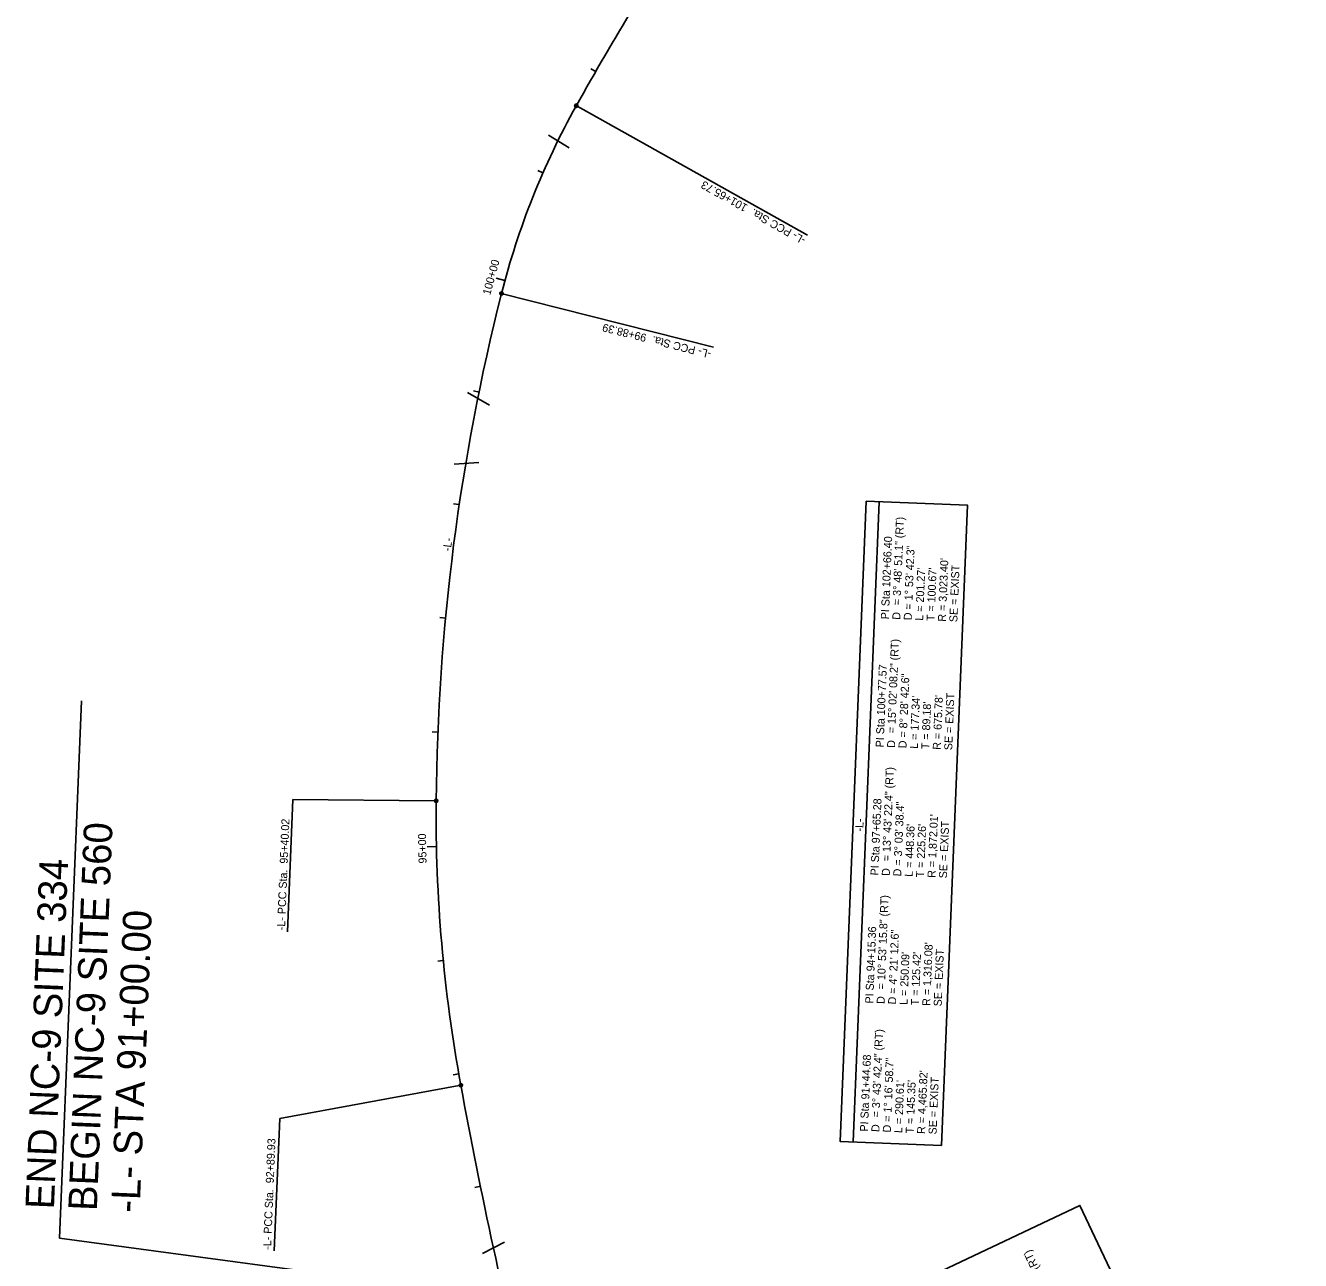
# Model space of a CAD drawing. Extents: x 1019959 to 1023888, y 635993 to 644996.
# Drawn here: x 1022230 to 1023345, y 641988 to 643068 of the extents above; entities that cross this region are included whole.
import ezdxf

# ---------------------------------------------------------------- set-up
doc = ezdxf.new("R2010")
doc.units = 0
for name, color, linetype in [('Cogo Default Point CELL', 7, 'Continuous'), ('COGO Default Point Elevation', 7, 'Continuous'), ('COGO Default Point Number', 7, 'Continuous'), ('Exist Other Culture Well CELL', 7, 'Continuous'), ('Exist Roads EOT', 7, 'Continuous'), ('Exist Structure Minor Pipes CMP 18 Inch Cogo Number', 7, 'Continuous'), ('Exist Structure Minor Pipes CMP 24 Inch Cogo Number', 7, 'Continuous'), ('Exist Utilities Power Pole CELL', 7, 'Continuous'), ('Exist Utilities Power Pole Cogo Elevation', 7, 'Continuous'), ('Exist Utilities Power Pole Cogo Number', 7, 'Continuous')]:
    doc.layers.add(name, color=color, linetype=linetype)

msp = doc.modelspace()

# ---------------------------------------------------------------- linework, layer by layer
at = {"layer": 'COGO Default Point Elevation'}
for p, q in [((1022728.6, 643027.5), (1022724.3, 643030)), ((1022682.4, 642938.9), (1022677.9, 642940.9)), ((1022626.6, 642747.3), (1022621.7, 642748.3)), ((1022609.3, 642648.8), (1022604.3, 642649.5)), ((1022597.2, 642549.5), (1022592.3, 642550)), ((1022590.5, 642449.8), (1022585.5, 642450)), ((1022595.3, 642250), (1022590.4, 642249.5)), ((1022608.9, 642150.9), (1022604, 642150.1)), ((1022627.8, 642052.7), (1022622.9, 642051.7))]:
    msp.add_line(p, q, dxfattribs=at)
at = {"layer": 'COGO Default Point Number'}
for p, q in [((1022649.2, 642844.7), (1022641.5, 642846.8)), ((1022589.3, 642349.8), (1022581.3, 642349.6))]:
    msp.add_line(p, q, dxfattribs=at)
at = {"layer": 'Exist Other Culture Well CELL'}
for p, q in [((1022259.6, 642007.4), (1022278.8, 642477.3)), ((1022648.9, 641955), (1022259.6, 642007.4))]:
    msp.add_line(p, q, dxfattribs=at)
at = {"layer": 'Exist Roads EOT'}
for p, q in [((1022710.4, 642998.4), (1022913.9, 642884.5)), ((1022855.3, 642917.3), (1022855.3, 642917.3)), ((1022644.8, 642833.8), (1022831.8, 642786.4)), ((1022831.8, 642786.4), (1022831.8, 642786.4)), ((1022463.6, 642390.9), (1022458.9, 642275.1)), ((1022587.6, 642389.8), (1022463.6, 642390.9)), ((1022609.2, 642140.7), (1022452.3, 642111.9)), ((1022452.3, 642111.9), (1022447.5, 641996.1))]:
    msp.add_line(p, q, dxfattribs=at)
for centre in [(1022711.7, 642997.7), (1022646.2, 642833.4), (1022589.1, 642389.8), (1022610.7, 642141)]:
    msp.add_circle(centre, 1.5, dxfattribs=at)
at = {"layer": 'Exist Structure Minor Pipes CMP 18 Inch Cogo Number'}
for centre, radius, start, end in [((1025349.8, 641520.8), 3023.4, 146.9441, 150.7582), ((1023301.4, 642667.6), 675.8, 150.7582, 165.7939), ((1024461, 642374), 1872, 165.7939, 179.5167), ((1023905.1, 642378.7), 1316.1, 179.5167, 190.4045), ((1027003, 642947.5), 4465.8, 190.4045, 194.1329)]:
    msp.add_arc(centre, radius, start, end, dxfattribs=at)
at = {"layer": 'Exist Structure Minor Pipes CMP 24 Inch Cogo Number'}
for p, q in [((1022687.2, 642971.8), (1022705.3, 642960.7)), ((1022616.5, 642747), (1022635.7, 642735.7)), ((1022604.8, 642684.3), (1022626.5, 642685.6)), ((1022629.7, 641993.8), (1022648.9, 642003.8))]:
    msp.add_line(p, q, dxfattribs=at)
at = {"layer": 'Exist Utilities Power Pole CELL'}
for centre, radius, start, end in [((1025349.8, 641520.8), 3023.4, 146.9441, 150.7582), ((1023301.4, 642667.6), 675.8, 150.7582, 165.7939), ((1024461, 642374), 1872, 165.7939, 179.5167), ((1023905.1, 642378.7), 1316.1, 179.5167, 190.4045), ((1027003, 642947.5), 4465.8, 190.4045, 194.1329)]:
    msp.add_arc(centre, radius, start, end, dxfattribs=at)
at = {"layer": 'Exist Utilities Power Pole Cogo Elevation'}
msp.add_line((1022953.7, 642091.4), (1022976.6, 642651.3), dxfattribs=at)
for points in [[(1023031.1, 642088.2), (1023053.9, 642648.2), (1022965.2, 642651.8), (1022942.4, 642091.9)], [(1023345.1, 641628.5), (1023152.1, 642036), (1022998.8, 641963.4), (1023191.8, 641555.9)]]:
    msp.add_lwpolyline(points, close=True, dxfattribs=at)

# ---------------------------------------------------------------- texts
at = {"layer": 'Cogo Default Point CELL'}
for s, rotation, p in [('100+00', 74.8093, (1022636.3, 642831.6)), ('95+00', 91.2592, (1022580.7, 642335))]:
    msp.add_text(s, height=7, rotation=rotation, dxfattribs=at).set_placement(p)
at = {"layer": 'Exist Other Culture Well CELL'}
for s, p in [('BEGIN NC-9 SITE 560', (1022292.2, 642030.8)), ('END NC-9 SITE 334', (1022254.7, 642032.3)), ('-L- STA 91+00.00', (1022329.6, 642029.2))]:
    msp.add_text(s, height=25, rotation=87.6648, dxfattribs=at).set_placement(p)
at = {"layer": 'Exist Roads EOT'}
for s, rotation, p in [('-L- PCC Sta.  101+65.73', 150.7582, (1022913, 642882.1)), ('-L- PCC Sta.  99+88.39', 165.7939, (1022830.1, 642783.4)), ('-L- PCC Sta.  95+40.02', 87.6648, (1022456.8, 642276.5)), ('-L- PCC Sta.  92+89.93', 87.6648, (1022444.6, 641997))]:
    msp.add_text(s, height=7, rotation=rotation, dxfattribs=at).set_placement(p)
at = {"layer": 'Exist Utilities Power Pole Cogo Elevation'}
for s, rotation, p in [('= 3%%d 48\' 51.1" (RT)', 87.6648, (1022995.2, 642560.8)), ('PI Sta 102+66.40', 87.6648, (1022985, 642548.4)), ('D = 1%%d 53\' 42.3"', 87.6648, (1023005, 642547.6)), ("L = 201.27'", 87.6648, (1023015, 642547.2)), ("T = 100.67'", 87.6648, (1023025, 642546.8)), ("R = 3,023.40'", 87.6648, (1023034.9, 642546.3)), ('SE = EXIST', 87.6648, (1023044.9, 642545.9)), ('D', 87.6648, (1022995, 642548)), ('= 15%%d 02\' 08.2" (RT)', 87.6648, (1022990.6, 642448.8)), ('PI Sta 100+77.57', 87.6648, (1022980.4, 642436.4)), ('D = 8%%d 28\' 42.6"', 87.6648, (1023000.4, 642435.6)), ("L = 177.34'", 87.6648, (1023010.4, 642435.2)), ("R = 675.78'", 87.6648, (1023030.4, 642434.3)), ('SE = EXIST', 87.6648, (1023040.4, 642433.9)), ("T = 89.18'", 87.6648, (1023020.4, 642434.8)), ('D', 87.6648, (1022990.4, 642436)), ('= 13%%d 43\' 22.4" (RT)', 87.6648, (1022986.1, 642336.8)), ('PI Sta 97+65.28', 87.6648, (1022975.9, 642324.4)), ('D = 3%%d 03\' 38.4"', 87.6648, (1022995.8, 642323.6)), ('-L-', 87.6648, (1022962.6, 642362.8)), ("L = 448.36'", 87.6648, (1023005.8, 642323.2)), ("T = 225.26'", 87.6648, (1023015.8, 642322.7)), ("R = 1,872.01'", 87.6648, (1023025.8, 642322.3)), ('SE = EXIST', 87.6648, (1023035.8, 642321.9)), ('D', 87.6648, (1022985.8, 642324)), ('= 10%%d 53\' 15.8" (RT)', 87.6648, (1022981.5, 642224.8)), ('PI Sta 94+15.36', 87.6648, (1022971.3, 642212.4)), ('D = 4%%d 21\' 12.6"', 87.6648, (1022991.3, 642211.6)), ("L = 250.09'", 87.6648, (1023001.3, 642211.2)), ("T = 125.42'", 87.6648, (1023011.3, 642210.7)), ("R = 1,316.08'", 87.6648, (1023021.2, 642210.3)), ('SE = EXIST', 87.6648, (1023031.2, 642209.9)), ('D', 87.6648, (1022981.3, 642212)), ('= 3%%d 43\' 42.4" (RT)', 87.6648, (1022976.9, 642112.8)), ('PI Sta 91+44.68', 87.6648, (1022966.7, 642100.4)), ('D = 1%%d 16\' 58.7"', 87.6648, (1022986.7, 642099.6)), ("L = 290.61'", 87.6648, (1022996.7, 642099.1)), ("T = 145.35'", 87.6648, (1023006.7, 642098.7)), ("R = 4,465.82'", 87.6648, (1023016.7, 642098.3)), ('SE = EXIST', 87.6648, (1023026.7, 642097.9)), ('D', 87.6648, (1022976.7, 642100)), ('= 3%%d 43\' 42.4" (RT)', 115.343, (1023141.8, 641927.9))]:
    msp.add_text(s, height=7, rotation=rotation, dxfattribs=at).set_placement(p)
at = {"layer": 'Exist Utilities Power Pole Cogo Number'}
msp.add_text('-L-', height=7, rotation=82.6553, dxfattribs=at).set_placement((1022601.8, 642607.9))

doc.saveas('drawing.dxf')
